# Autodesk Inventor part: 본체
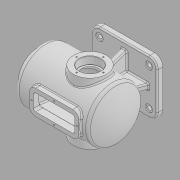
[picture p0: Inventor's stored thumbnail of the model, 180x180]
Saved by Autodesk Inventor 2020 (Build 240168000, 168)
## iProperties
Created: 2021-11
Part Number: 본체
Material: 일반
Document SubType Name: Modeling
Designer: Administrator
Density: 1 g/cm^3
Appearance: 기본값
Mass: 1280.15 g
Surface Area: 2412.62 cm^2
Volume: 1280.15 cm^3
Author: Administrator
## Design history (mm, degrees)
sketch "스케치1"
  geometry: L1 (-80, -65)-(80, -65); L2 (80, -65)-(80, 65); L3 (80, 65)-(-80, 65); L4 (-80, 65)-(-80, -65); L5 (-80, -65)-(80, 65); L6 (80, -65)-(-80, 65); 1 further point
  constraints: 12 end point, 2 midpoint, 2 parallel, 1 horizontal, 1 perpendicular
  dimensions: "d0" = 160 distance of L2.end L3.end; "d1" = 130 distance of L1.end L2.end
extrude "돌출1" new body sketch "스케치1" distance "d2" = 14; taper "d3" = 0 deg
sketch "스케치2"
  geometry: L1 (110, 114)-(-100, 114); L2 (110, 114)-(110, 161.5); L3 (110, 161.5)-(100, 161.5); L4 (100, 161.5)-(100, 179); L5 (100, 179)-(-75.993, 179); L6 (110, 114)-(110, 66.5); L7 (110, 66.5)-(100, 66.5); L8 (100, 66.5)-(100, 49); L9 (100, 49)-(-75.993, 49); L10 (80, 0)-(80, 14) reference; L11 (90, 146.5)-(90, 169); L12 (90, 169)-(-71.239, 169); L13 (90, 146.5)-(110, 146.5); A1 r 100 centre (0, 114) between (-75.993, 179) and (-75.993, 49); A2 r 90 centre (0, 114) between (-71.239, 169) and (-71.239, 59); 2 further points
  constraints: 24 end point, 5 point on circle, 4 perpendicular, 4 symmetric about line, 2 centre point, 2 horizontal, 1 point on line, 1 vertical, 2 other
  dimensions: "d4" = 114 vertical distance of point (0, 0) L1.start; "d5" = 100 radius of A1; "d6" = 210 distance from line of L1.end L2; "d7" = 130 distance between parallel lines of L9 L5; "d8" = 95 distance between parallel lines of L7 L3; "d9" = 30 distance between parallel lines of L10 L6; "d10" = 10 distance of L2.end L3.end; "d11" = 10 radial gap between concentric circles of A1 A2; "d80" = 65 diameter of L13 L1
revolve "회전1" sketch "스케치2" stored, may be unused: angle "d12" = 90 deg
sketch "스케치3"
  geometry: L1 (-7, -7)-(7, -7); L2 (7, -7)-(7, 7); L3 (7, 7)-(-7, 7); L4 (-7, 7)-(-7, -7); L5 (-7, -7)-(7, 7); L6 (7, -7)-(-7, 7); 1 further point
  constraints: 12 end point, 2 midpoint, 2 parallel, 1 horizontal, 1 perpendicular
  dimensions: "d13" = 14 distance of L3.end L2.end; "d14" = 14 distance of L2.end L1.end
extrude "돌출2" join sketch "스케치3" stored distance "d15" = 14; taper "d16" = 0 deg
sketch "스케치4"
  geometry: L1 (-75.993, 49)-(100, 49) reference; L2 (-80, 14)-(80, 14) reference; L3 (60, 14)-(47.261, 49); 1 further point
  constraints: 2 end point, 2 point on line
  dimensions: "d18" = 60 horizontal distance of L3.start point (0, 0); "d19" = 110 deg angle of L2 L3
feature "리브1" sketch "스케치4" dims "d20" = 1, "d21" = 14, "d22" = 0, "d23" = 0, "d24" = 1, "d25" = 1
sketch "스케치5"
  geometry: L1 (65, 14)-(-65, 14) reference; L2 (-50, 14)-(-33.809, 58.485); 2 further points
  constraints: 2 end point, 1 point on line, 2 other
  dimensions: "d26" = 50 horizontal distance of L2.start point (0, 0); "d27" = 110 deg angle of L1 L2
feature "리브2" sketch "스케치5" dims "d28" = 1, "d29" = 14, "d30" = 0, "d31" = 0, "d32" = 1, "d33" = 1
node "작업 평면1"
sketch "스케치6"
  geometry: L1 (110, 66.5)-(110, 161.5) reference; C1 r 40 at (-17, 114); 2 further points
  constraints: 1 centre point, 1 horizontal alignment, 1 midpoint
  dimensions: "d35" = 127 distance from line of L1 C1.centre; "d36" = 80 diameter of C1
extrude "돌출3" join sketch "스케치6" stored distance "d37" = 14; taper "d38" = 0 deg
sketch "스케치7"
  geometry: C1 r 40 at (0, 0) reference; 2 further points
  constraints: 1 coincident
hole "구멍1" sketch "스케치7" at (0, 0) diameter "d39" = 42; stored, may be unused: countersink angle "d43" = 90 deg, drill point angle "d45" = 118 deg; dims "d40" = 8, "d41" = 52, "d42" = 18, "d44" = 10
sketch "스케치8" dims "d46" = 65
  geometry: L1 (0, 0)-(0, -32.5); C1 r 26 at (0, 0) reference; 2 further points
  constraints: 2 coincident, 2 end point, 1 vertical, 1 vertical alignment, 2 other
hole "구멍2" sketch "스케치8" at (0, -32.5) diameter "d47" = 3.45873; stored, may be unused: countersink angle "d51" = 90 deg, drill point angle "d53" = 118 deg; dims "d48" = 11, "d49" = 52, "d50" = 18, "d52" = 13
node "작업 평면2"
sketch "스케치9"
  geometry: L1 (-60, 30)-(60, 30); L2 (60, 30)-(60, -30); L3 (60, -30)-(-60, -30); L4 (-60, -30)-(-60, 30); L5 (-110, 47.5)-(-110, -47.5) reference; 2 further points
  constraints: 8 end point, 2 parallel, 1 horizontal, 1 horizontal alignment, 1 midpoint, 1 perpendicular
  dimensions: "d58" = 50 distance between parallel lines of L4 L5; "d59" = 120 distance of L1.start L1.end; "d60" = 60 distance of L1.end L2.end
extrude "돌출4" join sketch "스케치9" stored distance "d61" = 14; taper "d62" = 0 deg
sketch "스케치10"
  geometry: L1 (-60, -30)-(60, -30) reference; L2 (60, -30)-(60, 30) reference; L3 (60, 30)-(-60, 30) reference; L4 (-60, 30)-(-60, -30) reference; L5 (-50, 20)-(50, 20); L6 (50, 20)-(50, -20); L7 (50, -20)-(-50, -20); L8 (-50, -20)-(-50, 20); 1 further point
  constraints: 8 end point, 3 other
  dimensions: "d63" = 10 distance between parallel lines of L3 L5
extrude "돌출5" cut sketch "스케치10" stored distance "d64" = 14; taper "d65" = 0 deg
fillet "모깎기1" dims "d66" = 15
fillet "모깎기2" dims "d67" = 5
sketch "스케치11"
  geometry: 5 further points
  constraints: 2 horizontal alignment, 2 vertical alignment
  dimensions: "d68" = 50 distance of point (0, -25) point (0, 25); "d69" = 25 distance of point (0, 0) point (0, 25); "d70" = 55 distance of point (0, 0) point (-55, 0); "d71" = 55 distance of point (55, 0) point (0, 0)
hole "구멍3" sketch "스케치11" at (0, 25), (-55, 0), (55, 0), (0, -25) diameter "d72" = 3.45873; stored, may be unused: countersink angle "d76" = 90 deg, drill point angle "d78" = 118 deg; dims "d73" = 9, "d74" = 52, "d75" = 18, "d77" = 11
sketch "스케치13" dims "d81" = 80
  geometry: L1 (0, 0)-(40, 0); C1 r 47.5 at (0, 0) reference; C2 r 32.5 at (0, 0) reference; 2 further points
  constraints: 2 coincident, 2 end point, 1 horizontal, 1 horizontal alignment, 2 other
hole "구멍4" sketch "스케치13" at (40, 0) diameter "d82" = 3.45873; stored, may be unused: countersink angle "d86" = 90 deg, drill point angle "d88" = 118 deg; dims "d83" = 11, "d84" = 52, "d85" = 18, "d87" = 13
fillet "모깎기3" dims "d92" = 10
fillet "모깎기4" dims "d93" = 10
fillet "모깎기5" dims "d94" = 3
fillet "모깎기6" dims "d95" = 3
fillet "모깎기7" dims "d96" = 3
fillet "모깎기8" dims "d97" = 3
fillet "모깎기9" dims "d98" = 20
sketch "스케치14"
  geometry: L1 (-80, 45)-(-80, -45) reference; L2 (60, 65)-(-60, 65) reference; L3 (80, -45)-(80, 45) reference; L4 (-60, -65)-(60, -65) reference; A1 r 20 centre (-60, -45) between (-80, -45) and (-60, -65) reference; A2 r 20 centre (-60, 45) between (-60, 65) and (-80, 45) reference; A3 r 20 centre (60, 45) between (80, 45) and (60, 65) reference; A4 r 20 centre (60, -45) between (60, -65) and (80, -45) reference; 5 further points
  constraints: 4 coincident
hole "구멍5" sketch "스케치14" at (60, -45), (-60, -45), (60, 45), (-60, 45) diameter "d99" = 9; stored, may be unused: countersink angle "d103" = 90 deg, drill point angle "d105" = 118 deg; dims "d100" = 11, "d101" = 18, "d102" = 2, "d104" = 13
fillet "모깎기10" dims "d106" = 3
fillet "모깎기11" dims "d107" = 3
chamfer "모따기1" distance "d108" = 1; stored, may be unused: second distance "d109" = 2, angle "d110" = 45 deg
fillet "모깎기12" dims "d111" = 3
sketch "스케치15"
  geometry: L1 (0, 0)-(120, 0) reference; L2 (39.261, 8.002)-(80.739, 8.002); L3 (80.739, 8.002)-(80.739, 1.998); L4 (80.739, 1.998)-(39.261, 1.998); L5 (39.261, 1.998)-(39.261, 8.002); L6 (39.261, 8.002)-(80.739, 1.998); L7 (80.739, 8.002)-(39.261, 1.998); 4 further points
  constraints: 4 end point, 3 midpoint, 1 vertical alignment, 2 other
  dimensions: "d112" = 5 distance of point (60, 5) point (60, 0)
feature "엠보싱1" sketch "스케치15" dims "d113" = 0.5, "d114" = 0
chamfer "모따기2" distance "d115" = 1; stored, may be unused: second distance "d116" = 2, angle "d117" = 45 deg
fillet "모깎기13" dims "d118" = 0.3
node "솔리드1"
mirror "미러1"
mirror "미러2"
mirror "미러3"
mirror "미러4"
pattern_circular "원형 패턴1" dims angle "d55" = 360 deg
mirror "미러5"
pattern_circular "원형 패턴2" dims angle "d90" = 360 deg
node "투영된 루프1"
node "투영된 루프2"
node "투영된 루프3"
feature "A9D066F2-1C7D-4E18-AEED-F7BC21143FA4" dims "d39" = 42, "d40" = 8, "d41" = 52, "d42" = 18, "d43" = 90 deg, "d44" = 10, "d45" = 118 deg
other parameters: "d34" = 75, "d57" = 184
